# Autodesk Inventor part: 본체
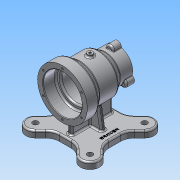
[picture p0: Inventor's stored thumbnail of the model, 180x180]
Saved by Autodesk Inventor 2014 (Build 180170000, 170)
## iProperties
Created: 2017-03
Part Number: 본체
Material: 알루미늄 6061
Document SubType Name: Modeling
Designer: NET
Density: 2.71 g/cm^3
Appearance: 알루미늄 - 평지
Mass: 1032.99 g
Surface Area: 868.356 cm^2
Volume: 381.179 cm^3
Author: NET
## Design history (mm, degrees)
sketch "스케치1"
  geometry: L1 (-59.214, 0)-(59.214, 0); L2 (-50, 0)-(-50, 45); L3 (-50, 45)-(-30, 45); L4 (-19, 36)-(15, 36); L5 (50, 27.5)-(50, 0); L6 (-50, 0)-(50, 0); L7 (50, 27.5)-(27, 27.5); L8 (27, 27.5)-(15, 36); L9 (-50, 35)-(-27, 35); L10 (-27, 35)-(-27, 26); L11 (-27, 26)-(20, 26); L12 (20, 26)-(20, 17.5); L13 (20, 17.5)-(50, 17.5); L14 (-19, 36)-(-30, 45); 2 further points
  constraints: 28 end point, 5 parallel, 5 perpendicular, 4 point on line, 2 coincident, 1 collinear, 1 horizontal, 1 midpoint
  dimensions: "d1" = 100 distance between parallel lines of L5 L2; "d2" = 65 distance from line of L2 L4.end; "d3" = 31 distance from line of L2 L4.start; "d4" = 20 distance of L2.end L3.end; "d6" = 50 distance from line of point (0, 0) L2; "d8" = 55 diameter of L7 L1; "d9" = 23 distance of L5.start L7.end; "d10" = 70 diameter of L9 L1; "d11" = 52 diameter of L11 L1; "d12" = 35 diameter of L13 L1; "d13" = 30 distance of L12.end L13.end; "d14" = 47 distance of L10.end L11.end; "d15" = 72 diameter of L4 L1; "d16" = 90 diameter of L3 L1
revolve "회전1" stored, may be unused: angle "d17" = 90 deg
sketch "스케치2"
  geometry: L1 (-50, -45)-(-50, 45) reference; L2 (-30, -45)-(-30, 45) reference; L3 (-19, -36)-(-19, 36) reference; L4 (15, -36)-(15, 36) reference; L5 (27, -27.5)-(27, 27.5) reference; L6 (50, -27.5)-(50, 27.5) reference; L7 (15, -36)-(27, -27.5) reference; L8 (-30, -45)-(-19, -36) reference; L9 (-37, 0)-(37, 0); L10 (37, 0)-(37, -82); L11 (37, -82)-(-37, -82); L12 (-37, -82)-(-37, 0); 3 further points
  constraints: 8 end point, 2 midpoint, 2 parallel, 1 coincident, 1 horizontal, 1 perpendicular, 1 vertical alignment
  dimensions: "d18" = 74 distance of L10.end L11.end; "d19" = 82 distance of L11.end L9.start
extrude "돌출1" join sketch "스케치2" stored distance "d20" = 8; taper "d21" = 0 deg
sketch "스케치3"
  geometry: L1 (-4, -44.822)-(-4, -82) reference; L2 (4, -82)-(4, -44.822) reference; L3 (-4, -82)-(4, -82) reference; L4 (-25, -70)-(25, -70); L5 (25, -70)-(12.657, 0); L6 (12.657, 0)-(-12.657, 0); L7 (-12.657, 0)-(-25, -70); A1 r 36 centre (0, 0) between (4, -35.777) and (-4, -35.777) reference; 3 further points
  constraints: 8 end point, 2 coincident, 2 midpoint, 2 parallel, 1 vertical alignment
  dimensions: "d22" = 100 deg angle of L4 L5; "d24" = 70 distance between parallel lines of L6 L4; "d133" = 25 distance of point (0, -70) L4.start
extrude "돌출2" join sketch "스케치3" stored distance "d25" = 8; taper "d26" = 0 deg
sketch "스케치5" dims "d38" = 140
  geometry: L1 (-41, 8)-(49, 8); L2 (49, 8)-(49, -82); L3 (49, -82)-(-41, -82); L4 (-41, -82)-(-41, 8); L5 (49, -82)-(-58.345, 25.345); L6 (49, -82)-(200.809, -82); L7 (-45.497, 12.497)-(-14.96, -18.04); L8 (-57.518, 0.477)-(-26.981, -30.061); L9 (-2.939, -6.019)-(-33.477, 24.518); L10 (-26.981, -43.939)-(-57.518, -74.477); L11 (-33.477, -98.518)-(-2.939, -67.981); L12 (10.939, -67.981)-(41.477, -98.518); L13 (65.518, -74.477)-(34.981, -43.939); L14 (34.981, -30.061)-(65.518, 0.477); L15 (41.477, 24.518)-(10.939, -6.019); L16 (-26.981, -43.939)-(-2.939, -67.981); L17 (10.939, -67.981)-(34.981, -43.939); L18 (34.981, -30.061)-(10.939, -6.019); L19 (-2.939, -6.019)-(-26.981, -30.061); A1 r 17 centre (-45.497, 12.497) between (-33.477, 24.518) and (-57.518, 0.477); A2 r 17 centre (-14.96, -18.04) between (-26.981, -30.061) and (-2.939, -6.019); A3 r 17 centre (-45.497, -86.497) between (-57.518, -74.477) and (-33.477, -98.518); A4 r 17 centre (53.497, -86.497) between (41.477, -98.518) and (65.518, -74.477); A5 r 17 centre (53.497, 12.497) between (65.518, 0.477) and (41.477, 24.518); 5 further points
  constraints: 40 end point, 10 point on circle, 5 centre point, 5 perpendicular, 4 tangent, 3 midpoint, 3 parallel, 2 horizontal, 2 point on line, 1 coincident, 1 equal length, 1 horizontal alignment, 1 vertical alignment, 36 other
  dimensions: "d36" = 90 distance of L2.end L3.end; "d37" = 90 distance of L1.end L2.end; "d39" = 135 deg angle of L6 L5; "d40" = 34 diameter of A2; "d43" = 360 deg dimension on point (4, -37) L7.start (derived)
extrude "돌출3" join sketch "스케치5" distance "d45" = 12; taper "d46" = 0 deg
sketch "스케치7"
  geometry: L1 (4, -31.096)-(4, -35.777) reference; L2 (4, -35.777)-(15, -35.777) reference; L3 (15, -35.777)-(15, -35.777) reference; L4 (15, -35.777)-(4, -35.777) reference; L5 (4, -35.777)-(4, -31.096) reference; L6 (4, -31.096)-(-4, -31.096) reference; L7 (-4, -31.096)-(-4, -35.777) reference; L8 (-4, -35.777)-(-19, -35.777) reference; L9 (-19, -35.777)-(-19, -35.777) reference; L10 (-19, -35.777)-(-4, -35.777) reference; L11 (-4, -35.777)-(-4, -31.096) reference; L12 (-4, -31.096)-(4, -31.096) reference; L13 (-19, 36)-(15, 36) reference; L14 (0, 48.55)-(0, -10.355); L15 (0, 40)-(-5, 40); L16 (-5, 40)-(-5, 30); L17 (-5, 30)-(0, 30); L18 (0, 40)-(0, 30); 1 further point
  constraints: 10 end point, 3 perpendicular, 2 point on line, 1 collinear, 1 parallel, 1 vertical alignment
  dimensions: "d50" = 5 distance between parallel lines of L18 L16; "d51" = 10 distance of L15.end L16.end; "d52" = 40 distance from line of L15 point (0, 0)
revolve "회전2" sketch "스케치7" stored, may be unused: angle "d53" = 90 deg
revolve "회전3" stored, may be unused: angle "d54" = 90 deg
fillet "모깎기1" dims "d55" = 3
fillet "모깎기2" dims "d56" = 3
sketch "스케치9"
  geometry: C1 r 5 at (0, 0) reference; 1 further point
  constraints: 1 coincident
hole "구멍1" sketch "스케치9" at (0, 0) diameter "d57" = 4.134; stored, may be unused: countersink angle "d61" = 90 deg, drill point angle "d63" = 0 deg; dims "d58" = 20, "d59" = 4, "d60" = 2, "d62" = 20
fillet "모깎기3" dims "d64" = 3
sketch "스케치10"
  geometry: L1 (27, 27.5)-(50, 27.5) reference; L2 (50, -27.5)-(50, 27.5) reference; L3 (27, -27.208)-(37, -27.208) reference; L4 (37, -27.208)-(37, -27.208) reference; L5 (37, -27.208)-(27, -27.208) reference; L6 (27, -27.208)-(27, -27.208) reference; L7 (50, 27.5)-(50, 34.5); L8 (50, 34.5)-(35, 34.5); L9 (35, 34.5)-(35, 27.5); L10 (29.174, 27.5)-(56.479, 27.5); L11 (35, 27.5)-(50, 27.5); 1 further point
  constraints: 10 end point, 3 perpendicular, 3 point on line, 1 collinear
  dimensions: "d65" = 15 distance of L7.end L8.end; "d66" = 7 distance of L2.end L7.end
revolve "회전4" sketch "스케치10" stored, may be unused: angle "d67" = 90 deg
sketch "스케치11"
  geometry: A1 r 7 centre (23.816, 41.25) between (26.516, 34.792) and (19.573, 46.817) reference; 1 further point
  constraints: 1 coincident
hole "구멍2" sketch "스케치11" at (23.816, 41.25) diameter "d71" = 3.242; stored, may be unused: countersink angle "d75" = 90 deg, drill point angle "d77" = 118 deg; dims "d72" = 9, "d73" = 4, "d74" = 2, "d76" = 11
fillet "모깎기4" dims "d81" = 3
fillet "모깎기5" dims "d82" = 1
chamfer "모따기1" distance "d83" = 1; stored, may be unused: second distance "d84" = 2, angle "d85" = 45 deg
chamfer "모따기2" distance "d86" = 1; stored, may be unused: second distance "d87" = 2, angle "d88" = 45 deg
sketch "스케치12" dims "d89" = 80
  geometry: C1 r 36 at (0, 0) reference; 2 further points
  constraints: 1 coincident, 1 vertical alignment, 2 other
hole "구멍3" sketch "스케치12" at (0, 40) diameter "d90" = 3.242; stored, may be unused: countersink angle "d94" = 90 deg, drill point angle "d96" = 118 deg; dims "d91" = 9, "d92" = 4, "d93" = 2, "d95" = 11
fillet "모깎기6" dims "d100" = 3
fillet "모깎기8" dims "d102" = 25
sketch "스케치15"
  geometry: 1 further point
sketch "스케치16"
  geometry: 1 further point
sketch "스케치17"
  geometry: L1 (106.518, 82.477)-(97.322, 73.281) reference; L2 (-4.497, 94.497)-(-4.497, -52.925); L3 (94.497, -4.497)-(-34.394, -4.497); L4 (-4.497, -4.497)-(45, 45); L5 (7.523, -16.518)-(57.021, 32.979); L6 (32.979, 57.021)-(-16.518, 7.523); A1 r 17 centre (94.497, -4.497) between (82.477, -16.518) and (106.518, 7.523) reference; A2 r 17 centre (-4.497, 94.497) between (7.523, 106.518) and (-16.518, 82.477) reference; A3 r 17 centre (-4.497, -4.497) between (-16.518, 7.523) and (7.523, -16.518); A4 r 17 centre (45, 45) between (57.021, 32.979) and (32.979, 57.021); 1 further point
  constraints: 12 end point, 4 point on circle, 4 tangent, 2 centre point, 2 parallel, 1 midpoint, 1 perpendicular, 1 point on line, 1 vertical
  dimensions: "d117" = 34 diameter of A4
extrude "돌출6" join sketch "스케치17" distance "d118" = 12; taper "d119" = 0 deg
sketch "스케치18"
  geometry: C1 r 5 at (-53.497, 12.497); C2 r 5 at (-53.497, -86.497); C3 r 5 at (45.497, -86.497); C4 r 5 at (45.497, 12.497); A1 r 14 centre (-53.497, 12.497) between (-43.598, 22.397) and (-63.397, 2.598) reference; 1 further point
  constraints: 4 centre point, 1 coincident
  dimensions: "d121" = 10 diameter of C1; "d122" = 10 diameter of C2; "d123" = 10 diameter of C3; "d124" = 10 diameter of C4
extrude "돌출7" cut sketch "스케치18" distance "d125" = 12; taper "d126" = 0 deg
sketch "스케치19"
  geometry: L1 (6.603, 8)-(-14.603, 8) reference; 2 further points
  constraints: 1 other
  dimensions: "d127" = 35 distance of point (-4, -37) point (31, -37); "d128" = 45 distance from line of L1 point (31, -37)
feature "엠보싱2" sketch "스케치19" dims "d1" = 100, "d2" = 65, "d3" = 31, "d4" = 20, "d6" = 50, "d8" = 55, "d9" = 23, "d10" = 70, "d11" = 52, "d12" = 35, "d13" = 30, "d14" = 47, "d15" = 72, "d16" = 90, "d129" = 0.5, "d130" = 0
fillet "모깎기11" dims "d131" = 3
fillet "모깎기12" dims "d132" = 3
fillet "모깎기13" dims "d142" = 25
fillet "모깎기14" dims "d143" = 3
fillet "모깎기15" dims "d144" = 3
node "솔리드1"
pattern_circular "원형 패턴1" dims angle "d69" = 360 deg
pattern_circular "원형 패턴2" dims angle "d79" = 360 deg
pattern_circular "원형 패턴3" dims angle "d98" = 360 deg
node "투영된 루프1"
node "투영된 루프2"
node "투영된 루프3"
node "투영된 루프4"
node "투영된 루프5"
